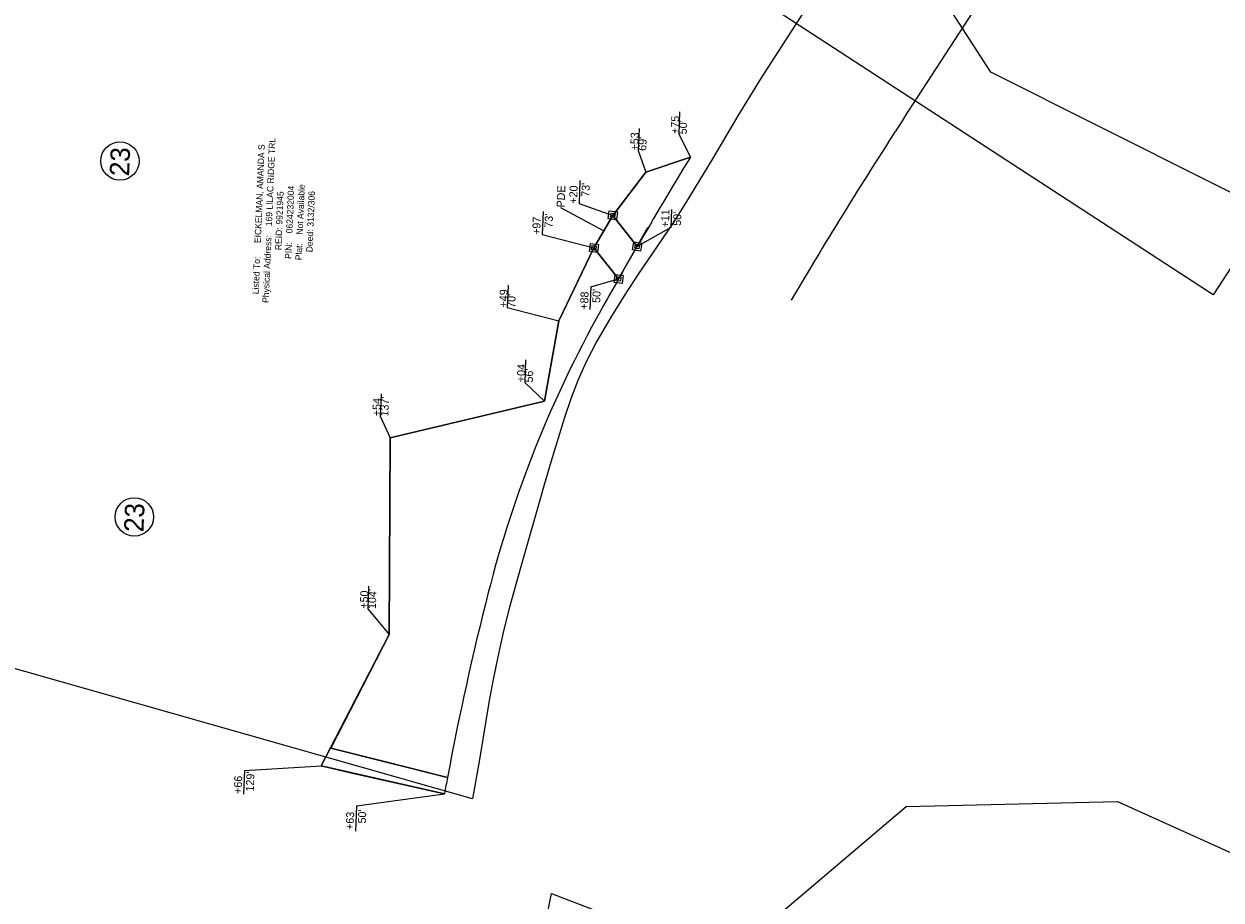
# Model space of a CAD drawing. Extents: x 1019969 to 1024963, y 638146 to 643978.
# Drawn here: x 1022308 to 1023056, y 642653 to 643201 of the extents above; entities that cross this region are included whole.
import ezdxf

# ---------------------------------------------------------------- set-up
doc = ezdxf.new("R2010")
doc.units = 0
for name, color, linetype in [('Old_Level_30', 7, 'Continuous'), ('Pattern 2', 7, 'Continuous'), ('Pattern 5', 7, 'Continuous'), ('Pattern 6', 7, 'Continuous'), ('Prop Easement Construction', 7, 'Continuous'), ('Prop Easement Construction Station Offsets', 7, 'Continuous'), ('Prop Easement Permanent Drainage', 7, 'Continuous'), ('Prop Easement Permanent Drainage Station Offsets', 7, 'Continuous'), ('Prop Parcel Number CELL', 7, 'Continuous'), ('Prop Parcel Owner Text', 7, 'Continuous'), ('Prop ROW Marker CELL', 7, 'Continuous'), ('Prop ROW Permanent Easement CELL', 7, 'Continuous'), ('Scratch_Level_2', 7, 'Continuous'), ('Scratch_Level_3', 7, 'Continuous'), ('Scratch_Level_4', 7, 'Continuous')]:
    doc.layers.add(name, color=color, linetype=linetype)

msp = doc.modelspace()

# ---------------------------------------------------------------- linework, layer by layer
at = {"layer": 'Old_Level_30'}
msp.add_lwpolyline([(1022806.31, 643226.63), (1022768.38, 643167.56), (1022753.81, 643143.87), (1022737.81, 643116.94), (1022721.12, 643089.19), (1022712.87, 643076.38), (1022691.5, 643044.75), (1022683.38, 643032.37), (1022674.19, 643017.62), (1022665.69, 643002.94), (1022659, 642990), (1022653.81, 642978.25), (1022649.38, 642966.88), (1022645.38, 642955.25), (1022636.81, 642927.19), (1022631.72, 642909.47), (1022631.68, 642909.42), (1022628.31, 642897.69), (1022617.8, 642861.12), (1022611.13, 642836.56), (1022607.38, 642821.75), (1022603.69, 642805.56), (1022600.81, 642791.31), (1022598.37, 642778.25), (1022592.31, 642741.44), (1022587.81, 642716.69), (1022073.5, 642863.06)], dxfattribs=at)
at = {"layer": 'Pattern 2'}
for p, q in [((1022690.81, 643062.17), (1022675.59, 643081.61)), ((1022663.79, 643061.22), (1022679.21, 643041.84))]:
    msp.add_line(p, q, dxfattribs=at)
for points in [[(1022675.59, 643081.61), (1022670.02, 643071.98), (1022663.79, 643061.22)], [(1022681.82, 643046.42), (1022690.8, 643062.14), (1022690.81, 643062.17)]]:
    msp.add_lwpolyline(points, dxfattribs=at)
msp.add_arc((1025349.82, 641520.77), 3073.4, 150.23767, 150.3361, dxfattribs=at)
at = {"layer": 'Pattern 6'}
for p, q in [((1022724.08, 643118.04), (1022696.22, 643108.65)), ((1022696.22, 643108.65), (1022675.59, 643081.61)), ((1022675.59, 643081.61), (1022690.81, 643062.17)), ((1022663.79, 643061.22), (1022641.81, 643015.67)), ((1022663.79, 643061.22), (1022663.79, 643061.22)), ((1022690.81, 643062.17), (1022690.86, 643062.11)), ((1022641.81, 643015.67), (1022632.89, 642965.32)), ((1022632.89, 642965.32), (1022536.49, 642942.49)), ((1022536.49, 642942.49), (1022535.89, 642819.57)), ((1022535.89, 642819.57), (1022499.41, 642748.42)), ((1022499.09, 642748.56), (1022493.26, 642737.3)), ((1022499.43, 642748.48), (1022499.09, 642748.56)), ((1022499.41, 642748.42), (1022499.43, 642748.48)), ((1022499.41, 642748.42), (1022572.29, 642730.19)), ((1022528.53, 642741.14), (1022499.41, 642748.42)), ((1022493.26, 642737.3), (1022513.73, 642732.69)), ((1022572.29, 642730.19), (1022528.53, 642741.14)), ((1022513.73, 642732.69), (1022570.39, 642719.93))]:
    msp.add_line(p, q, dxfattribs=at)
for points in [[(1022679.21, 643041.84), (1022697.54, 643073.95), (1022679.21, 643041.84)], [(1022690.81, 643062.17), (1022697.54, 643073.95), (1022690.81, 643062.17)]]:
    msp.add_lwpolyline(points, dxfattribs=at)
for centre, radius, start, end in [((1025349.82, 641520.77), 3073.4, 148.68738, 149.90023), ((1023829.99, 643972.56), 1480.05, 218.00639, 218.96513), ((1023690.58, 642457.72), 1167.93, 149.99173, 151.10262), ((1023301.36, 642667.58), 725.78, 150.75825, 165.79385), ((1024331.37, 642402.61), 1789.32, 165.66305, 169.45125), ((1024461.01, 642374.01), 1922.01, 169.32045, 169.63148)]:
    msp.add_arc(centre, radius, start, end, dxfattribs=at)
at = {"layer": 'Prop Easement Construction'}
for p, q in [((1022696.22, 643108.65), (1022724.08, 643118.04)), ((1022675.59, 643081.61), (1022696.22, 643108.65)), ((1022641.81, 643015.67), (1022663.79, 643061.22)), ((1022632.89, 642965.32), (1022641.81, 643015.67)), ((1022536.49, 642942.49), (1022632.89, 642965.32)), ((1022535.89, 642819.57), (1022536.49, 642942.49)), ((1022493.26, 642737.3), (1022535.89, 642819.57)), ((1022570.39, 642719.93), (1022493.26, 642737.3))]:
    msp.add_line(p, q, dxfattribs=at)
at = {"layer": 'Prop Easement Construction Station Offsets'}
for p, q in [((1022717.32, 643146.41), (1022716.75, 643132.42)), ((1022692, 643136.01), (1022691.43, 643122.09)), ((1022610.1, 643037.94), (1022609.52, 643023.91)), ((1022621.13, 642991.29), (1022620.55, 642977.2)), ((1022530.85, 642970.04), (1022530.27, 642955.96)), ((1022523, 642849.72), (1022522.43, 642835.57)), ((1022445.46, 642734.56), (1022444.85, 642719.68)), ((1022515.42, 642712.33), (1022514.78, 642696.51))]:
    msp.add_line(p, q, dxfattribs=at)
for points in [[(1022716.75, 643132.42), (1022724.08, 643118.04)], [(1022691.43, 643122.09), (1022696.22, 643108.65)], [(1022609.52, 643023.91), (1022641.81, 643015.67)], [(1022620.55, 642977.2), (1022632.89, 642965.32)], [(1022530.27, 642955.96), (1022536.49, 642942.49)], [(1022522.43, 642835.57), (1022535.89, 642819.57)], [(1022445.46, 642734.56), (1022493.26, 642737.3)], [(1022515.42, 642712.33), (1022570.39, 642719.93)]]:
    msp.add_lwpolyline(points, dxfattribs=at)
at = {"layer": 'Prop Easement Permanent Drainage'}
for p in [(1022663.79, 643061.22), (1022690.86, 643062.11)]:
    msp.add_line(p, (1022675.59, 643081.61), dxfattribs=at)
at = {"layer": 'Prop Easement Permanent Drainage Station Offsets'}
for p, q in [((1022655.05, 643103.31), (1022654.47, 643089.07)), ((1022632.02, 643083.99), (1022631.43, 643069.7)), ((1022712.3, 643085.2), (1022711.84, 643073.99)), ((1022679.21, 643041.84), (1022663.79, 643061.22)), ((1022661.86, 643036.95), (1022661.28, 643022.78))]:
    msp.add_line(p, q, dxfattribs=at)
for points in [[(1022654.47, 643089.07), (1022675.59, 643081.61)], [(1022642.91, 643086.56), (1022670.02, 643071.98)], [(1022711.84, 643073.99), (1022690.86, 643062.11)], [(1022631.43, 643069.7), (1022663.79, 643061.22)], [(1022661.86, 643036.95), (1022679.21, 643041.84)]]:
    msp.add_lwpolyline(points, dxfattribs=at)
at = {"layer": 'Prop Parcel Number CELL'}
for p, q in [((1022367.56, 643115.56), (1022367.56, 643115.56)), ((1022376.55, 642893.05), (1022376.55, 642893.05))]:
    msp.add_line(p, q, dxfattribs=at)
for centre in [(1022367.56, 643115.56), (1022376.55, 642893.05)]:
    msp.add_circle(centre, 12, dxfattribs=at)
at = {"layer": 'Prop ROW Marker CELL'}
for p, q in [((1022675.59, 643081.61), (1022675.59, 643081.61)), ((1022663.79, 643061.22), (1022663.79, 643061.22)), ((1022690.86, 643062.11), (1022690.86, 643062.11)), ((1022679.21, 643041.84), (1022679.21, 643041.84))]:
    msp.add_line(p, q, dxfattribs=at)
at = {"layer": 'Prop ROW Permanent Easement CELL'}
for points in [[(1022673.37, 643084.44), (1022678.42, 643083.84), (1022677.82, 643078.78), (1022672.76, 643079.38)], [(1022674.48, 643083.02), (1022677.01, 643082.72), (1022676.7, 643080.2), (1022674.18, 643080.5)], [(1022661.63, 643064.1), (1022666.67, 643063.39), (1022665.96, 643058.35), (1022660.92, 643059.06)], [(1022662.71, 643062.66), (1022665.23, 643062.3), (1022664.88, 643059.78), (1022662.36, 643060.14)], [(1022688.73, 643065.01), (1022693.76, 643064.23), (1022692.98, 643059.2), (1022687.95, 643059.98)], [(1022689.79, 643063.56), (1022692.31, 643063.17), (1022691.92, 643060.66), (1022689.4, 643061.05)], [(1022676.99, 643044.67), (1022682.04, 643044.06), (1022681.43, 643039), (1022676.37, 643039.62)], [(1022678.1, 643043.25), (1022680.62, 643042.95), (1022680.32, 643040.42), (1022677.79, 643040.73)]]:
    msp.add_lwpolyline(points, close=True, dxfattribs=at)
at = {"layer": 'Scratch_Level_2'}
msp.add_lwpolyline([(1022778.99, 643208.83), (1023083.87, 643677.31), (1023355.75, 643500.37), (1023050.87, 643031.89)], close=True, dxfattribs=at)
at = {"layer": 'Scratch_Level_3'}
msp.add_line((1022857.7, 643142.64), (1023194.35, 643659.93), dxfattribs=at)
msp.add_arc((1025349.82, 641520.77), 2973.4, 146.94406, 149.52869, dxfattribs=at)
at = {"layer": 'Scratch_Level_4'}
msp.add_lwpolyline([(1023375.37, 643414.25), (1023232.66, 643010.18), (1023186.87, 643033.19), (1022911.81, 643171.25), (1022876.86, 643225.56), (1022887.12, 643241.44), (1022914.18, 643282.44), (1022923.5, 643296.94), (1022932.63, 643311.19), (1022953.13, 643345.06), (1022956.89, 643351.1), (1022968.88, 643370.44), (1022986.68, 643397.63), (1023009.31, 643431.38), (1023083.62, 643548.06), (1023092.12, 643560.81), (1023152.81, 643521), (1023271.39, 643501.81), (1023289.88, 643484.25), (1023349.85, 643478.2), (1023369.37, 643476.25), (1023374.6, 643421.76)], close=True, dxfattribs=at)
msp.add_lwpolyline([(1022633.81, 642639.69), (1022637.36, 642657.47), (1022745.79, 642615.94), (1022858.89, 642712.06), (1022990.92, 642715.17), (1023277.52, 642585.71)], dxfattribs=at)

# ---------------------------------------------------------------- texts
at = {"layer": 'Pattern 5'}
for s, p in [('EICKELMAN, AMANDA S', (1022455.59, 643064.2)), ('169 LILAC RIDGE TRL', (1022462.53, 643074.73)), ('9921945', (1022469.07, 643075.75)), ('0624232004', (1022475.36, 643070.3)), ('Not Available', (1022481.83, 643069.45)), ('3132/306', (1022488.54, 643074.45)), ('REID:', (1022468.42, 643059.77)), ('Physical Address:', (1022460.57, 643026.77)), ('Deed:', (1022487.88, 643058.47)), ('PIN:', (1022474.7, 643054.31)), ('Plat:', (1022481.18, 643053.47)), ('Listed To:', (1022454.29, 643032.23))]:
    msp.add_text(s, height=4, rotation=87.66484, dxfattribs=at).set_placement(p)
at = {"layer": 'Prop Easement Construction Station Offsets'}
for s, p in [('+75', (1022716.72, 643132.42)), ("50'", (1022721.77, 643132.22)), ('+53', (1022691.41, 643122.09)), ("69'", (1022696.45, 643121.88)), ('+49', (1022609.5, 643023.92)), ("70'", (1022614.55, 643023.71)), ('+04', (1022620.53, 642977.2)), ("56'", (1022625.57, 642977)), ('+54', (1022530.25, 642955.96)), ("137'", (1022535.29, 642955.75)), ('+50', (1022522.4, 642835.57)), ("104'", (1022527.45, 642835.37)), ('+66', (1022443.6, 642719.79)), ("129'", (1022451.17, 642721.26)), ('+63', (1022513.56, 642697.21)), ("50'", (1022521.23, 642701.25))]:
    msp.add_text(s, height=5, rotation=87.66484, dxfattribs=at).set_placement(p)
at = {"layer": 'Prop Easement Permanent Drainage Station Offsets'}
for s, rotation, p in [('PDE', 87.66484, (1022645.41, 643086.46)), ('+20', 87.66877, (1022653.22, 643088.87)), ("73'", 87.66877, (1022660.9, 643093.13)), ('+97', 87.66877, (1022630.17, 643069.32)), ("73'", 87.66877, (1022637.86, 643073.81)), ('+11', 87.66877, (1022710.59, 643073.93)), ("50'", 87.66877, (1022718.14, 643075.02)), ('+88', 87.66877, (1022660.02, 643022.52)), ("50'", 87.66877, (1022667.7, 643026.77))]:
    msp.add_text(s, height=5, rotation=rotation, dxfattribs=at).set_placement(p)
at = {"layer": 'Prop Parcel Owner Text'}
for p in [(1022373.25, 643105.89), (1022382.24, 642883.38)]:
    msp.add_text('23', height=12.15, rotation=87.66484, dxfattribs=at).set_placement(p)

doc.saveas('drawing.dxf')
